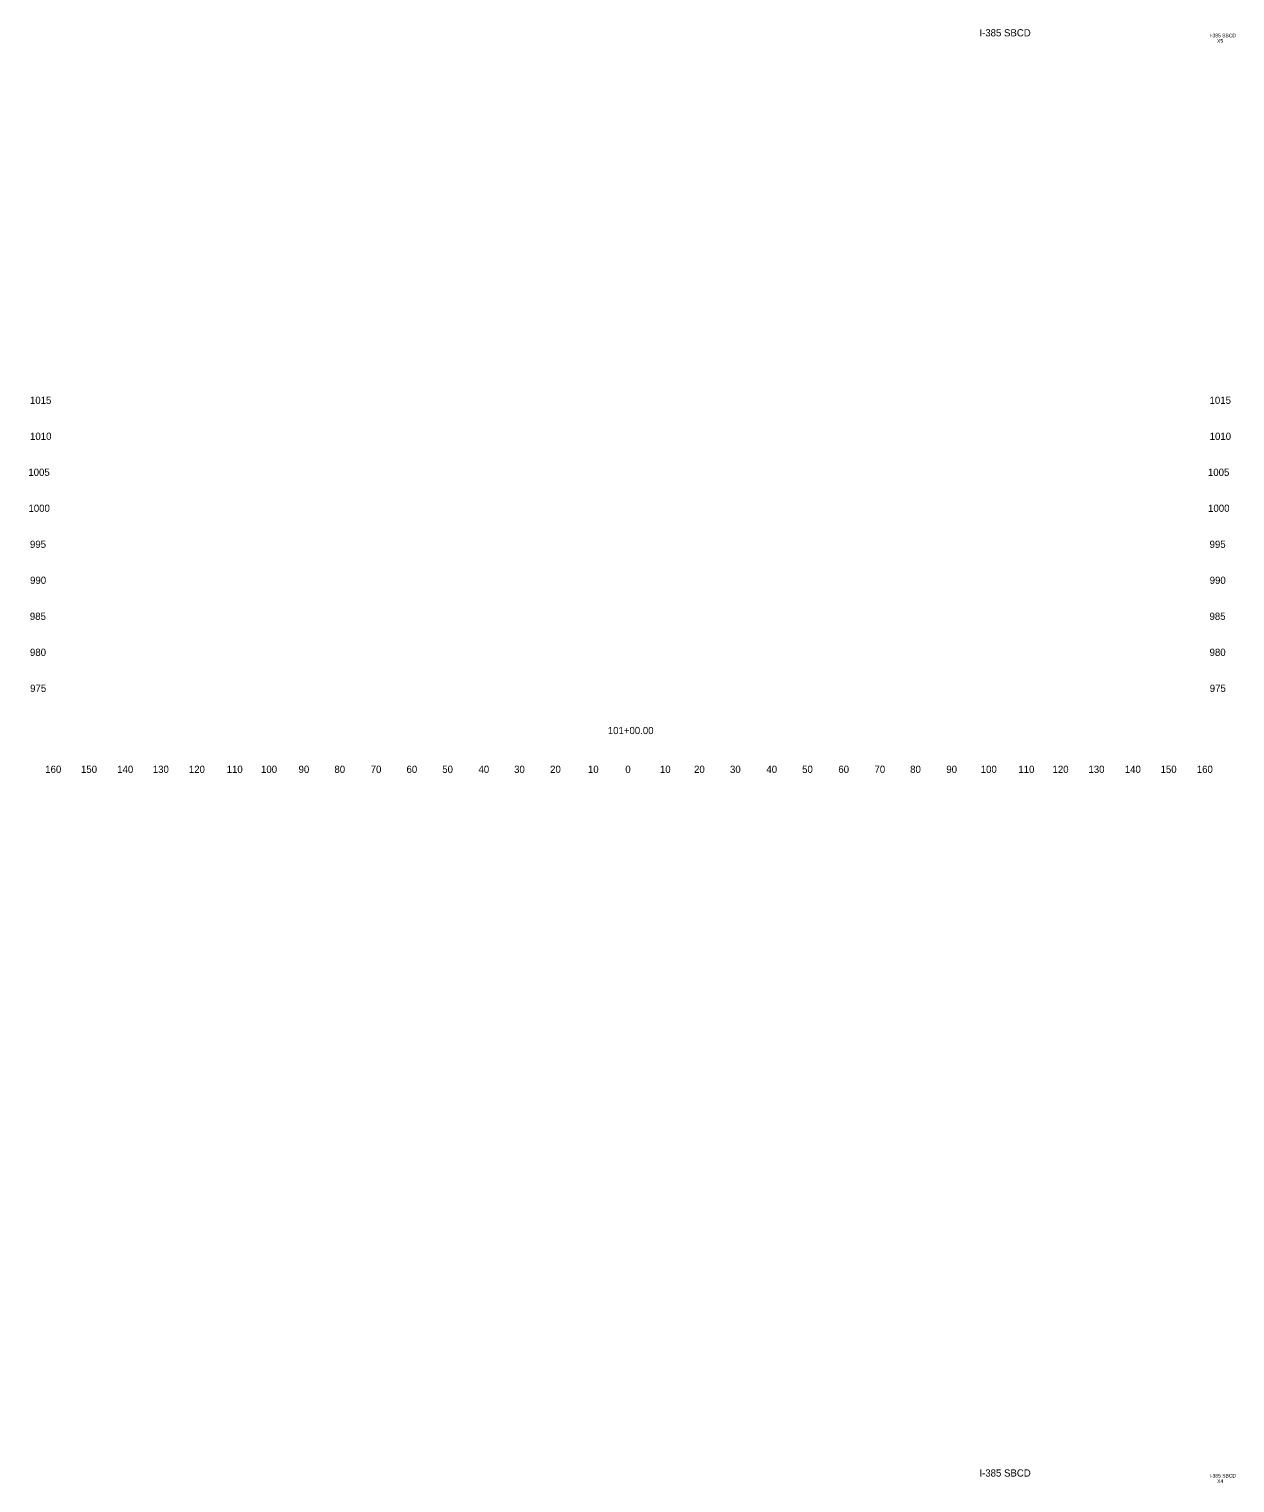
# Model space of a CAD drawing. Extents: x 4994 to 6876, y 4997 to 8804.
# Drawn here: x 4993.6 to 5328.7, y 6400.3 to 6804.1 of the extents above; entities that cross this region are included whole.
import ezdxf

# ---------------------------------------------------------------- set-up
doc = ezdxf.new("R2010")
doc.units = 0
for name, color, linetype in [('RD_SHT_ID', 7, 'Continuous'), ('RD_XS_TX_Offset', 7, 'Continuous'), ('RD_XS_TX_Station', 7, 'Continuous')]:
    doc.layers.add(name, color=color, linetype=linetype)

msp = doc.modelspace()

# ---------------------------------------------------------------- texts
at = {"layer": 'RD_SHT_ID'}
for s, height, p in [('I-385 SBCD', 2, (5257.69, 6802.06)), ('I-385 SBCD', 1, (5321.63, 6801.8)), ('X5', 1, (5323.74, 6800.3)), ('I-385 SBCD', 2, (5257.69, 6402.06)), ('I-385 SBCD', 1, (5321.63, 6401.8)), ('X4', 1, (5323.74, 6400.3))]:
    msp.add_text(s, height=height, dxfattribs=at).set_placement(p)
at = {"layer": 'RD_XS_TX_Offset'}
for s, p in [('1015', (4993.85, 6700)), ('1015', (5321.65, 6700)), ('1010', (4993.88, 6690)), ('1010', (5321.68, 6690)), ('1005', (4993.4, 6680)), ('1005', (5321.2, 6680)), ('1000', (4993.44, 6670)), ('1000', (5321.24, 6670)), ('995', (4993.86, 6660)), ('995', (5321.66, 6660)), ('990', (4993.89, 6650)), ('990', (5321.69, 6650)), ('985', (4993.83, 6640)), ('985', (5321.63, 6640)), ('980', (4993.86, 6630)), ('980', (5321.66, 6630)), ('975', (4993.91, 6620)), ('975', (5321.71, 6620)), ('160', (4998.1, 6597.5)), ('150', (5008.04, 6597.5)), ('140', (5018.1, 6597.5)), ('130', (5027.99, 6597.5)), ('120', (5038.01, 6597.5)), ('110', (5048.51, 6597.5)), ('100', (5058.07, 6597.5)), ('90', (5068.5, 6597.5)), ('80', (5078.46, 6597.5)), ('70', (5088.54, 6597.5)), ('60', (5098.5, 6597.5)), ('50', (5108.43, 6597.5)), ('40', (5118.5, 6597.5)), ('30', (5128.39, 6597.5)), ('20', (5138.4, 6597.5)), ('10', (5148.91, 6597.5)), ('0', (5159.3, 6597.5)), ('0', (5159.3, 6597.5)), ('10', (5168.91, 6597.5)), ('20', (5178.4, 6597.5)), ('30', (5188.39, 6597.5)), ('40', (5198.5, 6597.5)), ('50', (5208.43, 6597.5)), ('60', (5218.5, 6597.5)), ('70', (5228.54, 6597.5)), ('80', (5238.46, 6597.5)), ('90', (5248.5, 6597.5)), ('100', (5258.07, 6597.5)), ('110', (5268.51, 6597.5)), ('120', (5278.01, 6597.5)), ('130', (5287.99, 6597.5)), ('140', (5298.1, 6597.5)), ('150', (5308.04, 6597.5)), ('160', (5318.1, 6597.5))]:
    msp.add_text(s, height=2, dxfattribs=at).set_placement(p)
at = {"layer": 'RD_XS_TX_Station'}
msp.add_text('101+00.00', height=2, dxfattribs=at).set_placement((5154.43, 6608.27))

doc.saveas('drawing.dxf')
